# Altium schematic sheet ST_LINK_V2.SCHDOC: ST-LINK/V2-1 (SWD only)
size A4; CompanyName: STM; DocumentNumber: MB1142; Revision: B-01; SheetNumber: 2; SheetTotal: 5; PageSetup: Record=PageOptions|CenterHorizontal=True|CenterVertical=True|PrintScale=1.00|XCorrection=1.00|YCorrection=1.00|PrintKind=0|BorderSize=5000000|LeftOffset=0|BottomOffset=0|Orientation=2|PaperLength=1000|PaperWidth=1000|Scale=100|PaperSource=7|PrintQuality=-4|MediaType=1|DitherType=10|PaperKind=A4|PrintScaleMode=1; Project: STM32F3348-DISCO
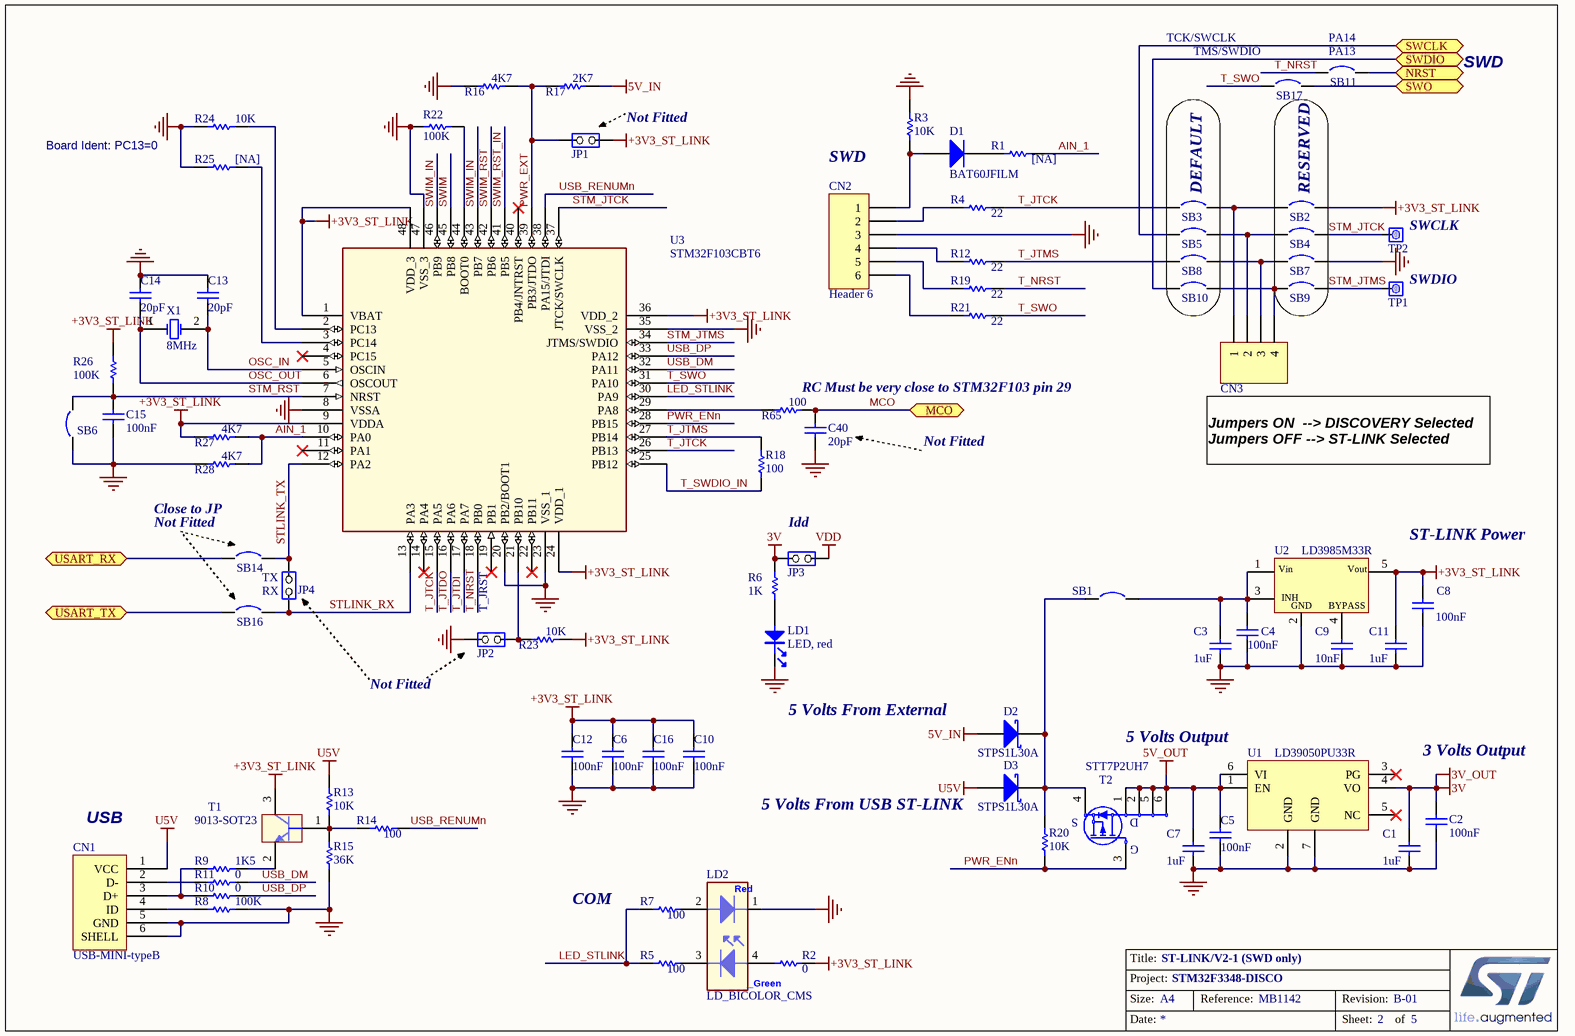
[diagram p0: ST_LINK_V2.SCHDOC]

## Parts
C1  1uF  [0603C]
C2  100nF  [0402C]
C3  1uF  [0603C]
C4  100nF  [0402C]
C5  100nF  [0402C]
C6  100nF  [0402C]
C7  1uF  [0603C]
C8  100nF  [0402C]
C9  10nF  [0603C]
C10  100nF  [0402C]
C11  1uF  [0603C]
C12  100nF  [0402C]
C13  20pF  [0402C]
C14  20pF  [0402C]
C15  100nF  [0402C]
C16  100nF  [0402C]
C40  20pF  [0402C]
CN1  USB-MINI-typeB  [USB-MINI-B-SMD]
CN2  Header 6  [HDR1X6]
CN3  Header 4  [Header 4]  (value not drawn)
D1  BAT60JFILM  [SOD323/A]
D2  STPS1L30A  [SMA]
D3  STPS1L30A  [SMA]
JP1  JP2  [SIP2/2.54]  (value not drawn)
JP2  Jumper2  [SIP2/2.54]  (value not drawn)
JP3  Jumper2  [SIP2/2.54]  (value not drawn)
JP4  Jumper2  [SIP2/2.54]  (value not drawn)
LD1  LED, red  [0603D]
LD2  LD_BICOLOR_CMS  [HSMF-A201]
R1  [NA]  [0402R]
R2  0  [0402R]
R3  10K  [0402R]
R4  22  [0402R]
R5  100  [0402R]
R6  1K  [0402R]
R7  100  [0402R]
R8  100K  [0402R]
R9  1K5  [0402R]
R10  0  [0402R]
R11  0  [0402R]
R12  22  [0402R]
R13  10K  [0402R]
R14  100  [0402R]
R15  36K  [0402R]
R16  4K7  [0402R]
R17  2K7  [0402R]
R18  100  [0402R]
R19  22  [0402R]
R20  10K  [0402R]
R21  22  [0402R]
R22  100K  [0402R]
R23  10K  [0402R]
R24  10K  [0402R]
R25  [NA]  [0402R]
R26  100K  [0402R]
R27  4K7  [0402R]
R28  4K7  [0402R]
R65  100  [0402R]
SB1  Circuit Breaker  [JP2_SMD]  (value not drawn)
SB2  Circuit Breaker  [JP2_SMD]  (value not drawn)
SB3  Circuit Breaker  [JP2_SMD]  (value not drawn)
SB4  Circuit Breaker  [JP2_SMD]  (value not drawn)
SB5  Circuit Breaker  [JP2_SMD]  (value not drawn)
SB6  Circuit Breaker  [JP2_SMD]  (value not drawn)
SB7  Circuit Breaker  [JP2_SMD]  (value not drawn)
SB8  Circuit Breaker  [JP2_SMD]  (value not drawn)
SB9  Circuit Breaker  [JP2_SMD]  (value not drawn)
SB10  Circuit Breaker  [JP2_SMD]  (value not drawn)
SB11  Circuit Breaker  [JP2_SMD]  (value not drawn)
SB14  Circuit Breaker  [JP2_SMD]  (value not drawn)
SB16  Circuit Breaker  [JP2_SMD]  (value not drawn)
SB17  Circuit Breaker  [JP2_SMD]  (value not drawn)
T1  9013-SOT23  [SOT23]
T2  STT7P2UH7  [SOT23-6L]
TP1  Test point 1 pin with hole  [SIP1/2.54]  (value not drawn)
TP2  Test point 1 pin with hole  [SIP1/2.54]  (value not drawn)
U1  LD39050PU33R  [DFN6_3x3]
U2  LD3985M33R  [SOT-23-5L]
U3  STM32F103CBT6  [QFP48 7X7]
X1  8MHz  [XTAL1]

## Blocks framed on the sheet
DEFAULT: SB3 SB5 SB8 SB10
RESERVED: SB2 SB4 SB7 SB9

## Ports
MCO, NRST, SWCLK, SWDIO, SWO, USART_RX, USART_TX

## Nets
3V: C1.2 C2.2 JP3.1(COMMON) R6.2 U1.4(VO)  [also labelled 3V_OUT]
5V_IN: D2.1(A) R17.2
5V_OUT: C5.2 C7.2 T2.1(S) T2.2(S) T2.5(D) T2.6(D) U1.1(EN) U1.6(VI)
+3V3_ST_LINK: C6.2 C8.2 C10.2 C11.1 C12.2 C16.1 JP1.2(NO) R2.2 R23.2 R26.2 R27.1 SB2.2 T1.3(C) U2.5(Vout) U3.1(VBAT) U3.9(VDDA) U3.24(VDD_1) U3.36(VDD_2) U3.48(VDD_3)
GND: C1.1 C2.1 C3.1 C4.1 C5.1 C6.1 C7.1 C8.1 C9.1 C10.1 C11.2 C12.1 C13.1 C14.1 C15.1 C16.2 C40.2 CN1.5(GND) CN1.6(SHELL) CN2.3 JP2.1(COMMON) LD1.2 LD2.1 R3.2 R8.2 R15.1 R16.1 R22.1 R24.1 R25.1 R28.1 SB6.1 SB7.2 U1.2(GND) U1.7(GND) U2.2(GND) U3.8(VSSA) U3.20(PB2/BOOT1) U3.23(VSS_1) U3.35(VSS_2) U3.47(VSS_3)
U5V: CN1.1(VCC) D3.1(A) R13.2
VDD: JP3.2(NO)
AIN_1: R1.2 R27.2 R28.2 U3.10(PA0)
LED_STLINK: R5.1 R7.1 U3.30(PA9)
MCO: C40.1 R65.2 ; port MCO
NRST: SB11.2 ; port NRST
OSC_IN: C13.2 U3.5(OSCIN) X1.2(OSC2)
OSC_OUT: C14.2 U3.6(OSCOUT) X1.1(OSC1)
PWR_ENn: R20.1 T2.3(G) U3.28(PB15)
PWR_EXT: JP1.1(COMMON) R16.2 R17.1 U3.39(PB3/JTDO)
STLINK_RX: JP4.1(COMMON) SB16.2 U3.13(PA3)
STLINK_TX: JP4.2(NO) SB14.2 U3.12(PA2)
STM_JTCK: SB4.2 TP2.1(COMMON) U3.37(JTCK/SWCLK)
STM_JTMS: SB9.2 TP1.1(COMMON) U3.34(JTMS/SWDIO)
STM_RST: C15.2 R26.1 SB6.2 U3.7(NRST)
SWCLK: SB5.1 ; port SWCLK
SWDIO: SB10.1 ; port SWDIO
SWIM: U3.45(PB8)
SWIM_IN: U3.43(PB7) U3.46(PB9)
SWIM_RST: U3.42(PB6)
SWIM_RST_IN: U3.41(PB5)
SWO: SB17.2 ; port SWO
T_JTCK: R4.2 SB3.1 U3.15(PA5) U3.26(PB13)
T_JTDI: U3.17(PA7)
T_JTDO: U3.16(PA6)
T_JTMS: R12.2 R18.2 SB8.1 U3.27(PB14)
T_NRST: R19.2 SB11.1 U3.18(PB0)
T_SWDIO_IN: R18.1 U3.25(PB12)
T_SWO: R21.2 SB17.1 U3.31(PA10)
USART_RX: SB14.1 ; port USART_RX
USART_TX: SB16.1 ; port USART_TX
USB_DM: R11.2 U3.32(PA11)
USB_DP: R10.2 U3.33(PA12)
USB_RENUMn: R14.2 U3.38(PA15/JTDI)
NetC3_2: C3.2 C4.2 SB1.2 U2.1(Vin) U2.3(CE)
NetC9_2: C9.2 U2.4(BYPASS)
NetCN1_2: CN1.2(D-) R11.1
NetCN1_3: CN1.3(D+) R9.1 R10.1
NetCN1_4: CN1.4(ID) R8.1
NetCN2_1: CN2.1 D1.1(A) R3.1
NetCN2_2: CN2.2 R4.1
NetCN2_4: CN2.4 R12.1
NetCN2_5: CN2.5 R19.1
NetCN2_6: CN2.6 R21.1
NetCN3_1: CN3.1 SB2.1 SB3.2
NetCN3_2: CN3.2 SB4.1 SB5.2
NetCN3_3: CN3.3 SB7.1 SB8.2
NetCN3_4: CN3.4 SB9.1 SB10.2
NetD1_2: D1.2(K) R1.1
NetD2_2: D2.2(K) D3.2(K) R20.2 SB1.1 T2.4(S)
NetJP2_2: JP2.2(NO) R23.1 U3.21(PB10)
NetLD1_1: LD1.1 R6.1
NetLD2_2: LD2.2 R7.2
NetLD2_3: LD2.3 R5.2
NetLD2_4: LD2.4 R2.1
NetR9_2: R9.2 T1.2(E)
NetR13_1: R13.1 R14.1 R15.2 T1.1(B)
NetR22_2: R22.2 U3.44(BOOT0)
NetR24_2: R24.2 U3.2(PC13)
NetR25_2: R25.2 U3.3(PC14)
NetR65_1: R65.1 U3.29(PA8)

Not connected (* = marked no-connect by the designer): U1 3(PG)* 5(NC)*; U3 4(PC15)* 11(PA1)* 14(PA4)* 19(PB1)* 22(PB11)* 40(PB4/JNTRST)*

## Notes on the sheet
- TCK/SWCLK
- (near SB11) PA14
- (near SB17) TMS/SWDIO
- (near SB11) PA13
- SWD
- Board Ident: PC13=0
- Not Fitted
- (near TP2) SWCLK
- (near TP1) SWDIO
- (near R65) RC Must be very close to STM32F103 pin 29
- Close to JP
- Jumpers ON  --> DISCOVERY Selected
  Jumpers OFF --> ST-LINK Selected
- (near SB14) Not Fitted
- TX
- Idd
- ST-LINK Power
- RX
- T_JRST
- 5 Volts From External
- (near U1) 5 Volts Output
- 3 Volts Output
- (near CN1) USB
- (near D3) 5 Volts From USB ST-LINK
- COM

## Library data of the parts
C1 C3 C7 C11 = Cap_1uF_X5R_10%_0603: Capacitor,1uF,16V,X5R,10%,0603,YAGEO; Manuf_Part_1: CC0603KRX5R7BB105
C2 C4-C6 C8 C10 C12 C15 C16 = Cap_100nF_X7R_10%_0402: Capacitor,100nF,16V,X7R,10%,0402,YAGEO; Manuf_Part_1: CC0402KRX7R7BB104
C9 = Cap_10nF_X7R_10%_0603: Capacitor,10nF,50V,X7R,10%,0603,YAGEO; Manuf_Part_1: CC0603KRX7R9BB103
C13 C14 = Cap_20pF_NPO_5%_0402: Capacitor,20pF,50V,NPO,5%,0402,YAGEO; Order: CC0402JRNPO9BN200
C40 = Cap_20pF_NPO_5%_0402: Capacitor,20pF,50V,NPO,5%,0402,YAGEO; Order: CC0402JRNPO9BN200; Fitted: NO
CN1 = USB-MINI-typeB connector: Manuf_Part_1: 5075BMR-05-SM; Manuf_Part_2: 218205M1110T; Manuf_2: lyconn; Description: USB,MINI-USB-5P/F, 5075BMR-05-M
CN2 = Header 6: Header, 6-Pin
CN3 = Header 4: Header, 4-Pin
D1 = BAT60JFILM: Manuf_1: STM; Provided: ST; ECCN_US/EU: EAR99/NEC; Ref St: 9151097
D2 D3 = STPS1L30A: Low Drop power Schottky rectifier; Manuf_1: STM; Provided: ST; Ref St: xxxxxxxx; ECCN_US/EU: EAR99/NEC
JP1 = JP2: Fitted: NO
JP2 JP4 = Jumper2: Fitted: NO
LD1 = LED_red: LED, red, 0603; Manuf_1: everlight; Manuf_Part_1: 19-213-R6C-AP1Q2B/3T; Description: LED,red,0603,19-213-R6C-AP1Q2B/3T,everlight; ECCN_US/EU: EAR99/NEC
LD2 = LD_BICOLOR_CMS: Bicolor Led; Manuf_Part_1: HSMF-A201-A00J1; Manuf_1: Avago Technologies; Manuf_2: everluck; Manuf_Part_2: LE-RGW35280; Ref St: xxxxxx; ECCN_US/EU: EAR99/NEC
R1 R25 = Resistor_ST: Resistor 0402 / 0603 / 0805; Description: Resistor 0402 or 0603 or 0805; Fitted: NO
R2-R13 R16-R24 R26-R28 R65 = Resistor_ST: Resistor 0402 / 0603 / 0805; Description: Resistor 0402 or 0603 or 0805
R14 R15 = Resistor_ST: Resistor 0402 / 0603 / 0805; Description: Resistor 0402 or 0603 or 0805; Value: 10K
SB1 SB3 SB5 SB8 SB10 SB11 = Circuit Breaker: Solder: YES
SB2 SB4 SB6 SB7 SB9 SB14 SB16 SB17 = Circuit Breaker: Solder: NO
T1 = 9013-SOT23: NPN Bipolar Transistor; Manuf_1: NXP; Manuf_Part_1: BSR14; Description: NPN Bipolar Transistor, SOT-23 Footprint; Order: 1081310; ECCN_US/EU: EAR99/NEC
T2 = STT7P2UH7: STripFET VII DeepGATE Power MOSFET, P-CHANNEL 20 V, 0.0146, 7 A - SOT23-6L; Manuf_1: STM; Provided: ST; Ref St: xxxxxxxx; ECCN_US/EU: EAR99/NEC
TP1 TP2 = TP1: Test Point; Fitted: NO
U1 = LD39050P: Ultra low drop-low , 500 mA low quiescent current; Manuf_1: STM; Provided: ST; ECCN_US/EU: EAR99/NEC; Ref St: xxxxxxxx
U2 = LD3985M33R: Ultra low drop-low noise BiCMOS voltage, regulators low ESR capacitors compatible; Manuf_1: STM; Provided: ST; Ref St: 9176161; ECCN_US/EU: EAR99/NEC
U3 = STM32F103CBT6: Medium-density performance line ARM-based 32-bit MCU with 128KB Flash; Manuf_1: STM; Ref St: xxxxxxxx; Provided: ST; ECCN_US/EU: 3A991A2/NEC
X1 = XTAL_8MHZ_20PPM: Crystal Oscillator,8Mhz,20PF,20PPM,-10-70 degree,DIP,HC-49S; Manuf_Part_1: HC-49S-C20QSA-8.000MHZ; ECCN_US/EU: EAR99/NEC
